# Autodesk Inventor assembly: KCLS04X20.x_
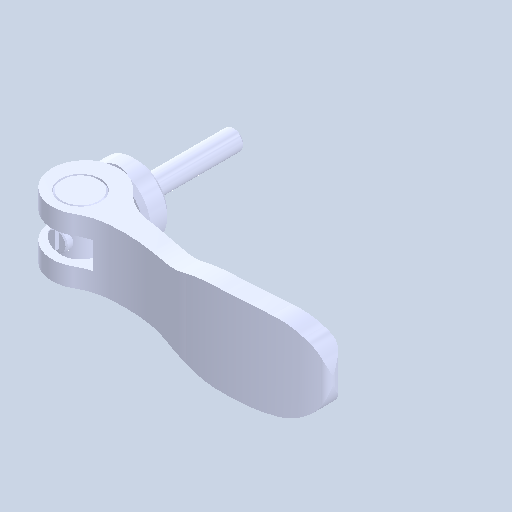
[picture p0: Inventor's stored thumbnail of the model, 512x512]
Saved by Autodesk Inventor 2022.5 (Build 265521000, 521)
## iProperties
Created: 2024-08
Part Number: KCLS04X20.x_
Document SubType Name: Assembly
Designer: ImaoCorp
Author: ImaoCorp
Sending System: SOLIDWORKS 2022-2022290
MC: AMD64
MC_MODEL: Intel64 Family 6 Model 60 Stepping 3, GenuineIntel
OS: Windows_NT
FRU: Parasolid Version 33.1, build 260,  4-25-2022
FORMAT: text
GUISE: transmit
KEY: FILEKCLS04X20.x_t
DATE: Thu Aug 29 10:54:16 2024
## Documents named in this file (5)
- Y:\5.更新分\2024年対応\1001_KCL\データ\kcls04x20\KCLS04X20.x_.iam
- Y:\5.更新分\2024年対応\1001_KCL\データ\kcls04x20\KCLS4X20_01.ipt
- Y:\5.更新分\2024年対応\1001_KCL\データ\kcls04x20\KCLS4X20_02.ipt
- Y:\5.更新分\2024年対応\1001_KCL\データ\kcls04x20\KCLS4X20_03.ipt
- Y:\5.更新分\2024年対応\1001_KCL\データ\kcls04x20\KCLS4X20_04.ipt
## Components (4 placed, 4 different names)
1. KCLS4X20_01
2. KCLS4X20_02
3. KCLS4X20_03
4. KCLS4X20_04
